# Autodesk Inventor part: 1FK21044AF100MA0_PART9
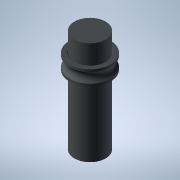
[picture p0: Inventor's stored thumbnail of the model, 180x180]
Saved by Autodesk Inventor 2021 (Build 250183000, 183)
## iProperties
Created: 2025-04
Part Number: 1FK21044AF100MA0_PART9
Material: Generic
Catalog Web Link: www.3dfindit.com
Description: -Servo synchronous motor
Document SubType Name: Modeling
Designer: psAdmin
Mass: 18.6788 g
Surface Area: 52.316 cm^2
Volume: 18.6788 cm^3
Density: 1 g/cm^3
Appearance: PSOLRGB-212-217-219
Category: PARTsolutions
Title: 1FK21044AF100MA0_PART9
Author: Cadenas PARTsolutions
Comments: Servo synchronous motor
Sending System: PARTsolutions
Preprocessor: ST-DEVELOPER v19.3
PSOL_IDENT_0: {$CADENAS_DATA/23d-libs/siemens_ag/_cat_/ec/e4/1fk21044af100ma0.prj},213 {VTYP=3D},{NB=1FK21044AF100
PSOL_IDENT_1: MA0_PART9},{LINA=1FK21044AF100MA0_PART9},{NN=1FK21044AF100MA0_PART9},{NOPRJ=TRUE},{DATE=19.08.2025 1
PSOL_IDENT_2: 4:01:05},{GEOMDATE=30.07.2025 02:01:01},{VERSION=},{LINEID=10},{WBVAR=},{WBNUMERIC=}  {NB=1FK21044AF
PSOL_IDENT_3: 100MA0_PART9},{LINA=1FK21044AF100MA0_PART9},{KT=DUMMY},{PREVIEW=../../../_pool_/cb/72/p_d211_xx_0043
PSOL_IDENT_4: 4j.png},{DESCSHORT=SIMOTICS S-1FK2 HD, SINAMICS S210 3AC 400V-480V, 1.27 Nm, 3000 rpm},{DESCLONG=SIM
PSOL_IDENT_5: OTICS S-1FK2 HD servo motor M0=1.27 Nm; PN = 0.4 kW at nN=3000 rpm (380-480 V); PN = 0.2 kW at nN=15
PSOL_IDENT_6: 00 rpm (200-240 V); with holding brake; degree of protection IP64; cylindrical shaft D19x40mm; absol
PSOL_IDENT_7: ute encoder 22-bit + 12-bit multiturn (encoder AM22DQC); with OCC interface; plug size M17, rotatabl
PSOL_IDENT_8: e; SIMOTICS S-1FK2 servomotorfor a wide range of uses in industrial environments. SIMOTICS S‑1FK2 se
PSOL_IDENT_9: rvomotors are compact synchronous motors with a high dynamic performance that set themselves apart a
PSOL_IDENT_10: s a result of their high power density, degree of protection and overload capability. The motors are
PSOL_IDENT_11: available in two variants: as High Dynamic variant (highest dynamic performance as a result of the
PSOL_IDENT_12: low intrinsic moment of inertia for applications demanding a high dynamic performance with low moved
PSOL_IDENT_13: masses) - and as Compact variant (precise and stable closed-loop control for medium up to large mov
PSOL_IDENT_14: ed masses as a result of a medium intrinsic moment of inertia). SIMOTICSS‑1FK2 servomotors fully exp
PSOL_IDENT_15: loit their strengths in a system with the SINAMICSS210 frequency converter and simple connection usi
PSOL_IDENT_16: ng the one cable connection (OCC). Advantages include the short control and positioning times, fast
PSOL_IDENT_17: and precise correction of disturbing quantities as well as stable control with a high dynamic perfor
PSOL_IDENT_18: mance. The servo motors can be configured to address a wide range of requirements. For example with
PSOL_IDENT_19: and without holding brake, IP64 or IP65 degree of protection, singleturn or multiturn absolute encod
PSOL_IDENT_20: ers - to name just a few. Further, the servomotors are available in different shaft heights extendin
PSOL_IDENT_21: g from 20 to 100. A shaft sealing ring is available to achieve an IP65 degree of protection and for
PSOL_IDENT_22: subsequent mounting at the motor or as spare part. SIMOTICS - the optimum motor for each and every m
PSOL_IDENT_23: otion control application.},{INTNO=195125043275},{SUPPLIERALTNO=1FK2104-4AF10-0MA0},{MANUID=1FK21044
PSOL_IDENT_24: AF100MA0},{MANUNAME=Siemens},{MANUTYPEDESC=Synchronous motor 1FK2-HD 1.27 NM},{AAU732=SIMOTICS},{AAO
PSOL_IDENT_25: 057=S-1FK2},{AAU734=SIMOTICS S-1FK2 HD servo motor M0=1.27 Nm; PN = 0.4 kW at nN=3000 rpm (380-480 V
PSOL_IDENT_26: ); PN = 0.2 kW at nN=1500 rpm (200-240 V); with holding brake; degree of protection IP64; cylindrica
PSOL_IDENT_27: l shaft D19x40mm; absolute encoder 22-bit + 12-bit multiturn (encoder AM22DQC); with OCC interface;
PSOL_IDENT_28: plug size M17, rotatable;},{AAW338=Synchronous motor 1FK2-HD 1.27 NM},{AAO742=SIMOTICS},{AAO663=4042
PSOL_IDENT_29: 948694015},{NOCUPEROU=1},{PRICEQUANTITY=1},{QUANTITYMIN=1},{QUANTITYINT=1},{CTN=85015100},{COO=DE},{
PSOL_IDENT_30: AAO676=1FK2104-4AF10-0MA0},{AAO677=Siemens AG},{ORDERUNIT=C62},{CONTENTUNIT=C62}
NB: 1FK21044AF100MA0_PART9
NT: Servo synchronous motor
NBSYN: $MANUID._PART9
LINA: 1FK21044AF100MA0_PART9
CATALOG: SIEMENS
PREVIEW: ../../../_pool_/cb/72/p_d211_xx_00434j.png
DESCSHORT: SIMOTICS S-1FK2 HD, SINAMICS S210 3AC 400V-480V, 1.27 Nm, 3000 rpm
DESCLONG: SIMOTICS S-1FK2 HD servo motor M0=1.27 Nm; PN = 0.4 kW at nN=3000 rpm (380-480 V); PN = 0.2 kW at nN=1500 rpm (200-240 V); with holding brake; degree of protect
INTNO: 195125043275
SUPPLIERALTNO: 1FK2104-4AF10-0MA0
MANUID: 1FK21044AF100MA0
MANUNAME: Siemens
MANUTYPEDESC: Synchronous motor 1FK2-HD 1.27 NM
AAU732: SIMOTICS
AAO057: S-1FK2
AAU734: SIMOTICS S-1FK2 HD servo motor M0=1.27 Nm; PN = 0.4 kW at nN=3000 rpm (380-480 V); PN = 0.2 kW at nN=1500 rpm (200-240 V); with holding brake; degree of protect
AAW338: Synchronous motor 1FK2-HD 1.27 NM
AAO742: SIMOTICS
AAO663: 4042948694015.0
NOCUPEROU: 1
PRICEQUANTITY: 1
QUANTITYMIN: 1
QUANTITYINT: 1
CTN: 85015100
COO: DE
ARTICLENO: 1FK21044AF100MA0_PART9
BOMINFO: 1FK21044AF100MA0_PART9
CREATOR: CADENAS GmbH
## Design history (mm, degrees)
feature "2025_04_17_15_33_01_0673"
body "Solid1"
